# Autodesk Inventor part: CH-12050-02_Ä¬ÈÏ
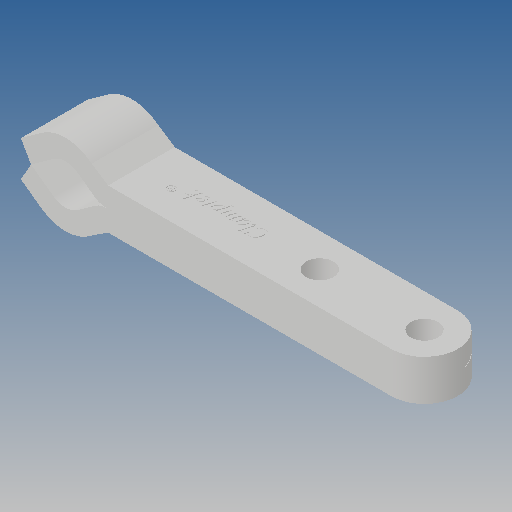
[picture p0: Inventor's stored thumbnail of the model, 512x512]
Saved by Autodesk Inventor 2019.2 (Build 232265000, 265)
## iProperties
Created: 2010-06
Part Number: CH-12050-02_Ä¬ÈÏ
Material: Ogólny
Document SubType Name: Modeling
Designer: CADENGINEERING4
Density: 1 g/cm^3
Appearance: Domyślna
Author: CADENGINEERING4
Revision Number: ÈÎºÎ
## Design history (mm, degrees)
feature "NONE"
feature "NONE:1"
node "Bryła1"
node "Bryła2"
